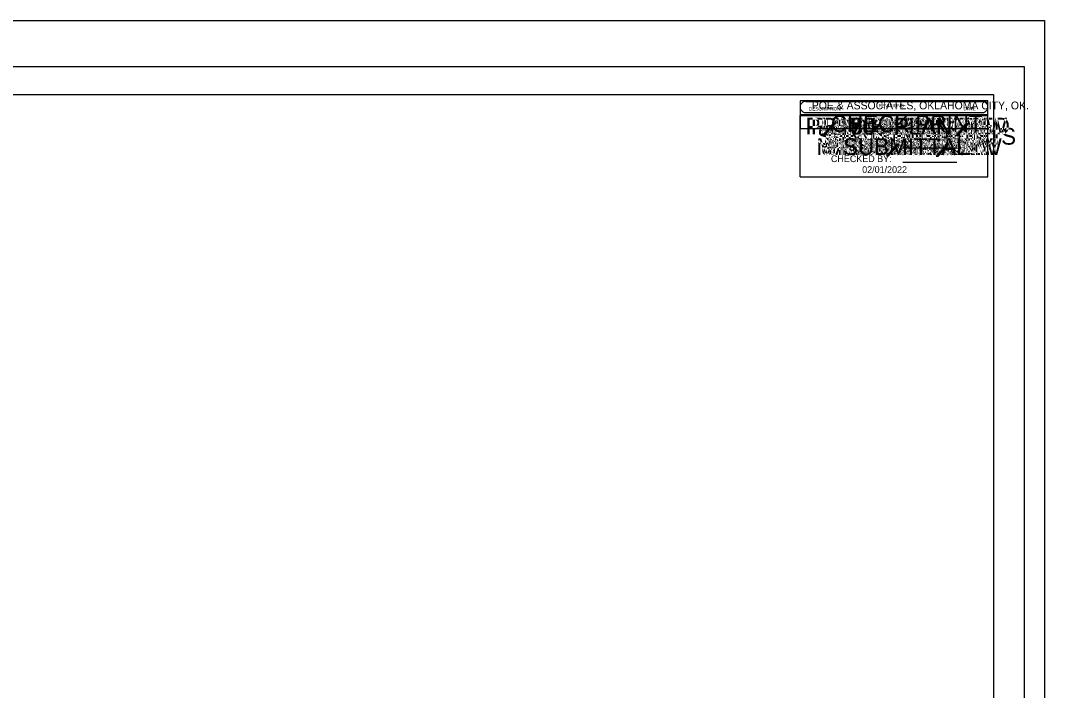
# Model space of a CAD drawing. Extents: x -93 to 177, y 25 to 84.
# Drawn here: x 8.45 to 26.81, y 37.37 to 49.37 of the extents above; entities that cross this region are included whole.
import ezdxf

# ---------------------------------------------------------------- set-up
doc = ezdxf.new("R2010")
doc.units = 0
for name, color, linetype in [('SHT_Date_Stamp', 7, 'Continuous'), ('SHT_Plot_Shape_Full', 7, 'Continuous'), ('SHT_Plot_Shape_Half', 7, 'Continuous'), ('SHT_Sheet_Border', 7, 'Continuous'), ('SHT_Stamp_30_Submit', 7, 'Continuous'), ('SHT_Stamp_60_Submit', 7, 'Continuous'), ('SHT_Stamp_70_Submit', 7, 'Continuous'), ('SHT_Stamp_90_Submit', 7, 'Continuous'), ('SHT_Stamp_Check_Print', 7, 'Continuous'), ('SHT_Stamp_Est_Inf', 7, 'Continuous'), ('SHT_Stamp_FFR', 7, 'Continuous'), ('SHT_Stamp_Info_Material', 7, 'Continuous'), ('SHT_Stamp_No_Const', 7, 'Continuous'), ('SHT_Stamp_No_Design', 7, 'Continuous'), ('SHT_Stamp_Plan_Hand', 7, 'Continuous'), ('SHT_Stamp_Pre_Plan', 7, 'Continuous'), ('SHT_Stamp_Prop_RW', 7, 'Continuous'), ('SHT_Stamp_Ret_Sub', 7, 'Continuous'), ('SHT_Stamp_Rev_Block', 7, 'Continuous'), ('SHT_Stamp_Rev_Prop_RW', 7, 'Continuous'), ('SHT_Stamp_Rev_Sheet', 7, 'Continuous'), ('SHT_Stamp_RW_Utilities_Meeting', 7, 'Continuous'), ('SHT_Stamp_RW_Utilities_Review', 7, 'Continuous'), ('SHT_Stamp_Send_Comments', 7, 'Continuous')]:
    doc.layers.add(name, color=color, linetype=linetype)

msp = doc.modelspace()

# ---------------------------------------------------------------- linework, layer by layer
at = {"layer": 'SHT_Plot_Shape_Full'}
msp.add_lwpolyline([(-9.19, 49.368), (26.81, 49.368), (26.81, 25.368), (-9.19, 25.368)], close=True, dxfattribs=at)
at = {"layer": 'SHT_Plot_Shape_Half'}
msp.add_lwpolyline([(-7.552, 48.543), (26.448, 48.543), (26.448, 26.543), (-7.552, 26.543)], close=True, dxfattribs=at)
at = {"layer": 'SHT_Sheet_Border'}
msp.add_lwpolyline([(25.898, 27.043), (-5.602, 27.043), (-5.602, 48.043), (25.898, 48.043)], close=True, dxfattribs=at)
at = {"layer": 'SHT_Stamp_30_Submit'}
for p, q in [((22.529, 47.919), (25.694, 47.919)), ((22.429, 47.669), (25.794, 47.669)), ((22.429, 46.57), (22.429, 47.669)), ((22.529, 47.719), (25.694, 47.719)), ((25.794, 46.57), (25.794, 47.669)), ((23.672, 47.331), (23.827, 47.503)), ((23.69, 47.331), (23.845, 47.503)), ((23.695, 47.331), (23.85, 47.503)), ((23.702, 47.331), (23.858, 47.503)), ((23.827, 47.503), (23.858, 47.503)), ((23.672, 47.331), (23.702, 47.331)), ((22.429, 46.57), (25.794, 46.57))]:
    msp.add_line(p, q, dxfattribs=at)
for centre, start, end in [((22.529, 47.819), 89.9952, 270), ((25.695, 47.819), 270, 90.0048)]:
    msp.add_arc(centre, 0.1, start, end, dxfattribs=at)
at = {"layer": 'SHT_Stamp_60_Submit'}
for p, q in [((22.529, 47.919), (25.694, 47.919)), ((22.429, 47.669), (25.794, 47.669)), ((22.429, 46.57), (22.429, 47.669)), ((22.529, 47.719), (25.694, 47.719)), ((25.794, 46.57), (25.794, 47.669)), ((23.672, 47.331), (23.827, 47.503)), ((23.69, 47.331), (23.845, 47.503)), ((23.695, 47.331), (23.85, 47.503)), ((23.702, 47.331), (23.858, 47.503)), ((23.827, 47.503), (23.858, 47.503)), ((23.672, 47.331), (23.702, 47.331)), ((22.429, 46.57), (25.794, 46.57))]:
    msp.add_line(p, q, dxfattribs=at)
for centre, start, end in [((22.529, 47.819), 89.9952, 270), ((25.695, 47.819), 270, 90.0048)]:
    msp.add_arc(centre, 0.1, start, end, dxfattribs=at)
at = {"layer": 'SHT_Stamp_70_Submit'}
for p, q in [((22.529, 47.919), (25.694, 47.919)), ((22.429, 47.669), (25.794, 47.669)), ((22.429, 46.57), (22.429, 47.669)), ((22.529, 47.719), (25.694, 47.719)), ((25.794, 46.57), (25.794, 47.669)), ((23.672, 47.331), (23.827, 47.503)), ((23.69, 47.331), (23.845, 47.503)), ((23.695, 47.331), (23.85, 47.503)), ((23.702, 47.331), (23.858, 47.503)), ((23.827, 47.503), (23.858, 47.503)), ((23.672, 47.331), (23.702, 47.331)), ((22.429, 46.57), (25.794, 46.57))]:
    msp.add_line(p, q, dxfattribs=at)
for centre, start, end in [((22.529, 47.819), 89.9952, 270), ((25.695, 47.819), 270, 90.0048)]:
    msp.add_arc(centre, 0.1, start, end, dxfattribs=at)
at = {"layer": 'SHT_Stamp_90_Submit'}
for p, q in [((22.529, 47.919), (25.694, 47.919)), ((22.429, 47.669), (25.794, 47.669)), ((22.429, 46.57), (22.429, 47.669)), ((22.529, 47.719), (25.694, 47.719)), ((25.794, 46.57), (25.794, 47.669)), ((23.672, 47.331), (23.827, 47.503)), ((23.69, 47.331), (23.845, 47.503)), ((23.695, 47.331), (23.85, 47.503)), ((23.702, 47.331), (23.858, 47.503)), ((23.827, 47.503), (23.858, 47.503)), ((23.672, 47.331), (23.702, 47.331)), ((22.429, 46.57), (25.794, 46.57))]:
    msp.add_line(p, q, dxfattribs=at)
for centre, start, end in [((22.529, 47.819), 89.9952, 270), ((25.695, 47.819), 270, 90.0048)]:
    msp.add_arc(centre, 0.1, start, end, dxfattribs=at)
at = {"layer": 'SHT_Stamp_Check_Print'}
for p, q in [((22.529, 47.919), (25.694, 47.919)), ((22.429, 47.669), (25.794, 47.669)), ((22.429, 46.57), (22.429, 47.669)), ((22.529, 47.719), (25.694, 47.719)), ((25.794, 46.57), (25.794, 47.669)), ((24.27, 47.088), (25.241, 47.088)), ((24.27, 46.832), (25.241, 46.832)), ((22.429, 46.57), (25.794, 46.57))]:
    msp.add_line(p, q, dxfattribs=at)
for centre, start, end in [((22.529, 47.819), 89.9952, 270), ((25.695, 47.819), 270, 90.0048)]:
    msp.add_arc(centre, 0.1, start, end, dxfattribs=at)
at = {"layer": 'SHT_Stamp_Est_Inf'}
for p, q in [((22.529, 47.919), (25.694, 47.919)), ((22.429, 47.669), (25.794, 47.669)), ((22.429, 46.57), (22.429, 47.669)), ((22.529, 47.719), (25.694, 47.719)), ((25.794, 46.57), (25.794, 47.669)), ((22.429, 46.57), (25.794, 46.57))]:
    msp.add_line(p, q, dxfattribs=at)
for centre, start, end in [((22.529, 47.819), 89.9952, 270), ((25.695, 47.819), 270, 90.0048)]:
    msp.add_arc(centre, 0.1, start, end, dxfattribs=at)
at = {"layer": 'SHT_Stamp_FFR'}
for p, q in [((22.529, 47.919), (25.694, 47.919)), ((22.429, 47.669), (25.794, 47.669)), ((22.429, 46.57), (22.429, 47.669)), ((22.529, 47.719), (25.694, 47.719)), ((25.794, 46.57), (25.794, 47.669)), ((22.429, 46.57), (25.794, 46.57))]:
    msp.add_line(p, q, dxfattribs=at)
for centre, start, end in [((22.529, 47.819), 89.9952, 270), ((25.695, 47.819), 270, 90.0048)]:
    msp.add_arc(centre, 0.1, start, end, dxfattribs=at)
at = {"layer": 'SHT_Stamp_Info_Material'}
for p, q in [((22.529, 47.919), (25.694, 47.919)), ((22.429, 47.669), (25.794, 47.669)), ((22.429, 46.57), (22.429, 47.669)), ((22.529, 47.719), (25.694, 47.719)), ((25.794, 46.57), (25.794, 47.669)), ((22.429, 46.57), (25.794, 46.57))]:
    msp.add_line(p, q, dxfattribs=at)
for centre, start, end in [((22.529, 47.819), 89.9952, 270), ((25.695, 47.819), 270, 90.0048)]:
    msp.add_arc(centre, 0.1, start, end, dxfattribs=at)
at = {"layer": 'SHT_Stamp_No_Const'}
for p, q in [((22.529, 47.919), (25.694, 47.919)), ((22.429, 47.669), (25.794, 47.669)), ((22.429, 46.57), (22.429, 47.669)), ((22.529, 47.719), (25.694, 47.719)), ((25.794, 46.57), (25.794, 47.669)), ((22.429, 46.57), (25.794, 46.57))]:
    msp.add_line(p, q, dxfattribs=at)
for centre, start, end in [((22.529, 47.819), 89.9952, 270), ((25.695, 47.819), 270, 90.0048)]:
    msp.add_arc(centre, 0.1, start, end, dxfattribs=at)
at = {"layer": 'SHT_Stamp_No_Design'}
for p, q in [((22.529, 47.919), (25.694, 47.919)), ((22.429, 47.669), (25.794, 47.669)), ((22.429, 46.57), (22.429, 47.669)), ((22.529, 47.719), (25.694, 47.719)), ((25.794, 46.57), (25.794, 47.669)), ((22.429, 46.57), (25.794, 46.57))]:
    msp.add_line(p, q, dxfattribs=at)
for centre, start, end in [((22.529, 47.819), 89.9952, 270), ((25.695, 47.819), 270, 90.0048)]:
    msp.add_arc(centre, 0.1, start, end, dxfattribs=at)
at = {"layer": 'SHT_Stamp_Plan_Hand'}
for p, q in [((22.529, 47.919), (25.694, 47.919)), ((22.429, 47.669), (25.794, 47.669)), ((22.429, 46.57), (22.429, 47.669)), ((22.529, 47.719), (25.694, 47.719)), ((25.794, 46.57), (25.794, 47.669)), ((22.429, 46.57), (25.794, 46.57))]:
    msp.add_line(p, q, dxfattribs=at)
for centre, start, end in [((22.529, 47.819), 89.9952, 270), ((25.695, 47.819), 270, 90.0048)]:
    msp.add_arc(centre, 0.1, start, end, dxfattribs=at)
at = {"layer": 'SHT_Stamp_Pre_Plan'}
for p, q in [((22.529, 47.919), (25.694, 47.919)), ((22.429, 47.669), (25.794, 47.669)), ((22.429, 46.57), (22.429, 47.669)), ((22.529, 47.719), (25.694, 47.719)), ((25.794, 46.57), (25.794, 47.669)), ((22.429, 46.57), (25.794, 46.57))]:
    msp.add_line(p, q, dxfattribs=at)
for centre, start, end in [((22.529, 47.819), 89.9952, 270), ((25.695, 47.819), 270, 90.0048)]:
    msp.add_arc(centre, 0.1, start, end, dxfattribs=at)
at = {"layer": 'SHT_Stamp_Prop_RW'}
for p, q in [((22.529, 47.919), (25.694, 47.919)), ((22.429, 47.669), (25.794, 47.669)), ((22.429, 46.57), (22.429, 47.669)), ((22.529, 47.719), (25.694, 47.719)), ((25.794, 46.57), (25.794, 47.669)), ((23.975, 46.942), (24.167, 47.155)), ((23.997, 46.942), (24.189, 47.155)), ((24.004, 46.942), (24.196, 47.155)), ((24.013, 46.942), (24.205, 47.155)), ((24.167, 47.155), (24.205, 47.155)), ((23.975, 46.942), (24.013, 46.942)), ((22.429, 46.57), (25.794, 46.57))]:
    msp.add_line(p, q, dxfattribs=at)
for centre, start, end in [((22.529, 47.819), 89.9952, 270), ((25.695, 47.819), 270, 90.0048)]:
    msp.add_arc(centre, 0.1, start, end, dxfattribs=at)
at = {"layer": 'SHT_Stamp_Ret_Sub'}
for p, q in [((22.529, 47.919), (25.694, 47.919)), ((22.429, 47.669), (25.794, 47.669)), ((22.429, 46.57), (22.429, 47.669)), ((22.529, 47.719), (25.694, 47.719)), ((25.794, 46.57), (25.794, 47.669)), ((22.429, 46.57), (25.794, 46.57))]:
    msp.add_line(p, q, dxfattribs=at)
for centre, start, end in [((22.529, 47.819), 89.9952, 270), ((25.695, 47.819), 270, 90.0048)]:
    msp.add_arc(centre, 0.1, start, end, dxfattribs=at)
at = {"layer": 'SHT_Stamp_Rev_Block'}
for p, q in [((25.794, 47.928), (22.429, 47.928)), ((22.429, 47.928), (22.429, 47.428)), ((25.794, 47.428), (25.794, 47.928)), ((25.794, 47.678), (22.429, 47.678)), ((25.794, 47.428), (22.429, 47.428))]:
    msp.add_line(p, q, dxfattribs=at)
at = {"layer": 'SHT_Stamp_Rev_Prop_RW'}
for p, q in [((22.529, 47.919), (25.694, 47.919)), ((22.429, 47.669), (25.794, 47.669)), ((22.429, 46.57), (22.429, 47.669)), ((22.529, 47.719), (25.694, 47.719)), ((25.794, 46.57), (25.794, 47.669)), ((24.866, 46.939), (25.058, 47.152)), ((24.888, 46.939), (25.08, 47.152)), ((24.894, 46.939), (25.086, 47.152)), ((24.903, 46.939), (25.095, 47.152)), ((25.058, 47.152), (25.095, 47.152)), ((24.866, 46.939), (24.903, 46.939)), ((22.429, 46.57), (25.794, 46.57))]:
    msp.add_line(p, q, dxfattribs=at)
for centre, start, end in [((22.529, 47.819), 89.9952, 270), ((25.695, 47.819), 270, 90.0048)]:
    msp.add_arc(centre, 0.1, start, end, dxfattribs=at)
at = {"layer": 'SHT_Stamp_Rev_Sheet'}
for p, q in [((22.529, 47.919), (25.694, 47.919)), ((22.429, 47.669), (25.794, 47.669)), ((22.429, 46.57), (22.429, 47.669)), ((22.529, 47.719), (25.694, 47.719)), ((25.794, 46.57), (25.794, 47.669)), ((22.429, 46.57), (25.794, 46.57))]:
    msp.add_line(p, q, dxfattribs=at)
for centre, start, end in [((22.529, 47.819), 89.9952, 270), ((25.695, 47.819), 270, 90.0048)]:
    msp.add_arc(centre, 0.1, start, end, dxfattribs=at)
at = {"layer": 'SHT_Stamp_RW_Utilities_Meeting'}
for p, q in [((22.529, 47.919), (25.694, 47.919)), ((22.429, 47.669), (25.794, 47.669)), ((22.429, 46.57), (22.429, 47.669)), ((22.529, 47.719), (25.694, 47.719)), ((25.794, 46.57), (25.794, 47.669)), ((22.831, 47.308), (23.023, 47.522)), ((22.853, 47.308), (23.045, 47.522)), ((22.859, 47.308), (23.051, 47.522)), ((22.868, 47.308), (23.06, 47.522)), ((23.023, 47.522), (23.06, 47.522)), ((22.831, 47.308), (22.868, 47.308)), ((22.429, 46.57), (25.794, 46.57))]:
    msp.add_line(p, q, dxfattribs=at)
for centre, start, end in [((22.529, 47.819), 89.9952, 270), ((25.695, 47.819), 270, 90.0048)]:
    msp.add_arc(centre, 0.1, start, end, dxfattribs=at)
at = {"layer": 'SHT_Stamp_RW_Utilities_Review'}
for p, q in [((22.529, 47.919), (25.694, 47.919)), ((22.429, 47.669), (25.794, 47.669)), ((22.429, 46.57), (22.429, 47.669)), ((22.529, 47.719), (25.694, 47.719)), ((25.794, 46.57), (25.794, 47.669)), ((25.219, 47.308), (25.411, 47.522)), ((25.241, 47.308), (25.433, 47.522)), ((25.247, 47.308), (25.439, 47.522)), ((25.257, 47.308), (25.449, 47.522)), ((25.411, 47.522), (25.449, 47.522)), ((25.219, 47.308), (25.257, 47.308)), ((22.429, 46.57), (25.794, 46.57))]:
    msp.add_line(p, q, dxfattribs=at)
for centre, start, end in [((22.529, 47.819), 89.9952, 270), ((25.695, 47.819), 270, 90.0048)]:
    msp.add_arc(centre, 0.1, start, end, dxfattribs=at)
at = {"layer": 'SHT_Stamp_Send_Comments'}
for p, q in [((22.529, 47.919), (25.694, 47.919)), ((22.429, 47.669), (25.794, 47.669)), ((22.429, 46.57), (22.429, 47.669)), ((22.529, 47.719), (25.694, 47.719)), ((25.794, 46.57), (25.794, 47.669)), ((22.429, 46.57), (25.794, 46.57))]:
    msp.add_line(p, q, dxfattribs=at)
for centre, start, end in [((22.529, 47.819), 89.9952, 270), ((25.695, 47.819), 270, 90.0048)]:
    msp.add_arc(centre, 0.1, start, end, dxfattribs=at)

# ---------------------------------------------------------------- texts
at = {"layer": 'SHT_Date_Stamp'}
msp.add_text('02/01/2022', height=0.12, dxfattribs=at).set_placement((23.542, 46.638))
at = {"layer": 'SHT_Stamp_30_Submit'}
for s, height, p in [('POE & ASSOCIATES, OKLAHOMA CITY, OK.', 0.14, (22.639, 47.776)), ('30   PLAN', 0.3, (23.331, 47.327)), ('O', 0.153, (23.637, 47.416)), ('O', 0.153, (23.789, 47.331)), ('SUBMITTAL', 0.3, (23.2, 46.96))]:
    msp.add_text(s, height=height, dxfattribs=at).set_placement(p)
at = {"layer": 'SHT_Stamp_60_Submit'}
for s, height, p in [('POE & ASSOCIATES, OKLAHOMA CITY, OK.', 0.14, (22.639, 47.776)), ('60   PLAN', 0.3, (23.324, 47.327)), ('O', 0.153, (23.637, 47.416)), ('O', 0.153, (23.789, 47.331)), ('SUBMITTAL', 0.3, (23.2, 46.96))]:
    msp.add_text(s, height=height, dxfattribs=at).set_placement(p)
at = {"layer": 'SHT_Stamp_70_Submit'}
for s, height, p in [('POE & ASSOCIATES, OKLAHOMA CITY, OK.', 0.14, (22.639, 47.776)), ('70   PLAN', 0.3, (23.324, 47.327)), ('O', 0.153, (23.637, 47.416)), ('O', 0.153, (23.789, 47.331)), ('SUBMITTAL', 0.3, (23.2, 46.96))]:
    msp.add_text(s, height=height, dxfattribs=at).set_placement(p)
at = {"layer": 'SHT_Stamp_90_Submit'}
for s, height, p in [('POE & ASSOCIATES, OKLAHOMA CITY, OK.', 0.14, (22.639, 47.776)), ('90   PLAN', 0.3, (23.324, 47.327)), ('O', 0.153, (23.637, 47.416)), ('O', 0.153, (23.789, 47.331)), ('SUBMITTAL', 0.3, (23.2, 46.96))]:
    msp.add_text(s, height=height, dxfattribs=at).set_placement(p)
at = {"layer": 'SHT_Stamp_Check_Print'}
for s, height, p in [('POE & ASSOCIATES, OKLAHOMA CITY, OK.', 0.14, (22.639, 47.777)), ('CHECK PRINT', 0.3, (22.981, 47.37)), ('REVISED BY:', 0.12, (22.982, 47.087)), ('CHECKED BY:', 0.12, (22.982, 46.832))]:
    msp.add_text(s, height=height, dxfattribs=at).set_placement(p)
at = {"layer": 'SHT_Stamp_Est_Inf'}
for s, height, p in [('POE & ASSOCIATES, OKLAHOMA CITY, OK.', 0.14, (22.639, 47.777)), ('BASED ON EST.', 0.3, (22.86, 47.327)), ('INFORMATION', 0.3, (22.981, 46.96))]:
    msp.add_text(s, height=height, dxfattribs=at).set_placement(p)
at = {"layer": 'SHT_Stamp_FFR'}
for s, height, p in [('POE & ASSOCIATES, OKLAHOMA CITY, OK.', 0.14, (22.639, 47.777)), ('FINAL FIELD', 0.3, (23.08, 47.327)), ('REVIEW', 0.3, (23.508, 46.96))]:
    msp.add_text(s, height=height, dxfattribs=at).set_placement(p)
at = {"layer": 'SHT_Stamp_Info_Material'}
for s, height, p in [('POE & ASSOCIATES, OKLAHOMA CITY, OK.', 0.14, (22.639, 47.777)), ('INFORMATION', 0.3, (22.981, 47.327)), ('MATERIAL ONLY', 0.3, (22.723, 46.96))]:
    msp.add_text(s, height=height, dxfattribs=at).set_placement(p)
at = {"layer": 'SHT_Stamp_No_Const'}
for s, height, p in [('POE & ASSOCIATES, OKLAHOMA CITY, OK.', 0.14, (22.639, 47.777)), ('NOT TO BE USED', 0.3, (22.669, 47.327)), ('FOR CONST.', 0.3, (23.16, 46.96))]:
    msp.add_text(s, height=height, dxfattribs=at).set_placement(p)
at = {"layer": 'SHT_Stamp_No_Design'}
for s, height, p in [('POE & ASSOCIATES, OKLAHOMA CITY, OK.', 0.14, (22.639, 47.777)), ('NOT TO BE USED', 0.3, (22.669, 47.327)), ('FOR DESIGN', 0.3, (23.142, 46.96))]:
    msp.add_text(s, height=height, dxfattribs=at).set_placement(p)
at = {"layer": 'SHT_Stamp_Plan_Hand'}
for s, height, p in [('POE & ASSOCIATES, OKLAHOMA CITY, OK.', 0.14, (22.639, 47.777)), ('PLAN-IN-HAND', 0.3, (22.913, 47.144))]:
    msp.add_text(s, height=height, dxfattribs=at).set_placement(p)
at = {"layer": 'SHT_Stamp_Pre_Plan'}
for s, height, p in [('POE & ASSOCIATES, OKLAHOMA CITY, OK.', 0.14, (22.639, 47.777)), ('PRELIMINARY', 0.3, (22.997, 47.327)), ('PLANS', 0.3, (23.604, 46.96))]:
    msp.add_text(s, height=height, dxfattribs=at).set_placement(p)
at = {"layer": 'SHT_Stamp_Prop_RW'}
for s, height, p in [('POE & ASSOCIATES, OKLAHOMA CITY, OK.', 0.14, (22.639, 47.777)), ('PROPOSED', 0.3, (23.338, 47.327)), ('R W', 0.3, (23.77, 46.96))]:
    msp.add_text(s, height=height, dxfattribs=at).set_placement(p)
at = {"layer": 'SHT_Stamp_Ret_Sub'}
for s, height, p in [('POE & ASSOCIATES, OKLAHOMA CITY, OK.', 0.14, (22.639, 47.777)), ('RET. SUBMITTED', 0.3, (22.847, 47.327)), ('MATERIALS', 0.3, (23.188, 46.96))]:
    msp.add_text(s, height=height, dxfattribs=at).set_placement(p)
at = {"layer": 'SHT_Stamp_Rev_Block'}
for s, p in [('DESCRIPTION', (22.588, 47.756)), ('REVISIONS', (23.837, 47.815)), ('DATE', (25.358, 47.76))]:
    msp.add_text(s, height=0.06, dxfattribs=at).set_placement(p)
at = {"layer": 'SHT_Stamp_Rev_Prop_RW'}
for s, height, p in [('POE & ASSOCIATES, OKLAHOMA CITY, OK.', 0.14, (22.639, 47.777)), ('REVISED', 0.3, (23.466, 47.327)), ('PROPOSED R W', 0.3, (22.88, 46.96))]:
    msp.add_text(s, height=height, dxfattribs=at).set_placement(p)
at = {"layer": 'SHT_Stamp_Rev_Sheet'}
for s, height, p in [('POE & ASSOCIATES, OKLAHOMA CITY, OK.', 0.14, (22.639, 47.777)), ('REVISED SHEET', 0.3, (22.863, 47.144))]:
    msp.add_text(s, height=height, dxfattribs=at).set_placement(p)
at = {"layer": 'SHT_Stamp_RW_Utilities_Meeting'}
for s, height, p in [('POE & ASSOCIATES, OKLAHOMA CITY, OK.', 0.14, (22.639, 47.776)), ('R W & UTILITIES', 0.3, (22.623, 47.327)), ('MEETING', 0.3, (23.392, 46.96))]:
    msp.add_text(s, height=height, dxfattribs=at).set_placement(p)
at = {"layer": 'SHT_Stamp_RW_Utilities_Review'}
for s, height, p in [('POE & ASSOCIATES, OKLAHOMA CITY, OK.', 0.14, (22.639, 47.776)), ('PRELIMINARY R W', 0.3, (22.528, 47.327)), ('& UTIL.  REVIEW', 0.3, (22.811, 46.96))]:
    msp.add_text(s, height=height, dxfattribs=at).set_placement(p)
at = {"layer": 'SHT_Stamp_Send_Comments'}
for s, height, p in [('POE & ASSOCIATES, OKLAHOMA CITY, OK.', 0.14, (22.639, 47.777)), ('SEND COMMENTS', 0.3, (22.734, 47.144))]:
    msp.add_text(s, height=height, dxfattribs=at).set_placement(p)

doc.saveas('drawing.dxf')
